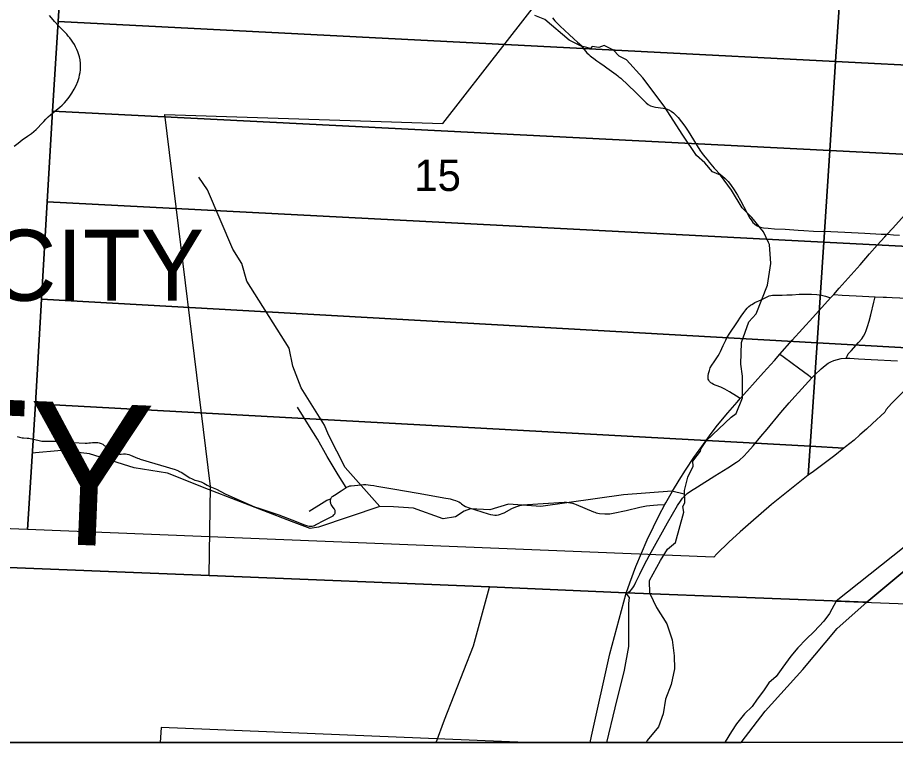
# Model space of a CAD drawing. Extents: x 0 to 34, y 0 to 22.
# Drawn here: x 25.938 to 27.11, y 14.1 to 15.067 of the extents above; entities that cross this region are included whole.
import ezdxf

# ---------------------------------------------------------------- set-up
doc = ezdxf.new("R2010")
doc.units = 0
for name, color, linetype in [('GM_X_City_Street', 7, 'Continuous'), ('GM_X_Corporation', 7, 'Continuous'), ('GM_X_Corporation_Text', 7, 'Continuous'), ('GM_X_County_Road', 7, 'Continuous'), ('GM_X_County_Text', 7, 'Continuous'), ('GM_X_Major_River', 7, 'Continuous'), ('GM_X_Minor_River', 7, 'Continuous'), ('GM_X_Section', 7, 'Continuous'), ('GM_X_Section_Text', 7, 'Continuous'), ('GM_X_State_Route', 7, 'Continuous'), ('GM_X_State_Shield', 7, 'Continuous'), ('GM_X_Township_Road', 7, 'Continuous'), ('SH_Cut_Line', 7, 'Continuous'), ('SH_Data', 7, 'Continuous')]:
    doc.layers.add(name, color=color, linetype=linetype)

msp = doc.modelspace()

# ---------------------------------------------------------------- linework, layer by layer
at = {"layer": 'GM_X_City_Street'}
for points in [[(26.6519, 15.0666), (26.6552, 15.0627), (26.6583, 15.0594), (26.6618, 15.0561), (26.6687, 15.0496), (26.6742, 15.0444), (26.6805, 15.0385), (26.6856, 15.034), (26.688, 15.0319), (26.6897, 15.0301), (26.6909, 15.0288), (26.6922, 15.0275), (26.6944, 15.0244), (26.6961, 15.0219), (26.6978, 15.0201), (26.7005, 15.0176), (26.7023, 15.016), (26.7042, 15.0144), (26.7072, 15.0122), (26.7112, 15.0094), (26.7153, 15.0065), (26.7208, 15.0026), (26.7244, 15.0001), (26.7309, 14.9954), (26.7339, 14.9932), (26.7368, 14.991), (26.7393, 14.9891), (26.7407, 14.9879), (26.7431, 14.986), (26.7454, 14.9839), (26.7507, 14.9789), (26.765, 14.9651), (26.7728, 14.9572), (26.7768, 14.9533), (26.7798, 14.9511), (26.783, 14.9493), (26.786, 14.9482), (26.7896, 14.9473), (26.7995, 14.9461), (26.8037, 14.9451), (26.8072, 14.9439), (26.8105, 14.9421), (26.8135, 14.9399), (26.8163, 14.9374), (26.8196, 14.9338), (26.8242, 14.9279), (26.8285, 14.9219), (26.833, 14.9152), (26.8487, 14.8901), (26.8518, 14.8856), (26.8551, 14.8812), (26.8583, 14.8775), (26.861, 14.8741), (26.8678, 14.8661), (26.8703, 14.8633), (26.8741, 14.8593), (26.8764, 14.8572), (26.8788, 14.8553), (26.8821, 14.8526), (26.8835, 14.8514), (26.8864, 14.8484), (26.8893, 14.8444), (26.8942, 14.8372), (26.8988, 14.8299), (26.9029, 14.8229), (26.9113, 14.807), (26.9155, 14.7993), (26.9178, 14.7957), (26.9194, 14.7937), (26.9216, 14.7916), (26.924, 14.7897), (26.9268, 14.7883), (26.9297, 14.7873), (26.9334, 14.7866), (26.9396, 14.7859), (26.9483, 14.7853), (26.9625, 14.7846), (26.98, 14.7834), (26.9874, 14.7829), (27.0004, 14.7822), (27.0233, 14.7815), (27.042, 14.7807), (27.0687, 14.7794), (27.0904, 14.7782), (27.0986, 14.7778), (27.1069, 14.7772), (27.1149, 14.7767)], [(26.9025, 14.5586), (26.8973, 14.5619), (26.8883, 14.5675), (26.8819, 14.5713), (26.8768, 14.5738), (26.8704, 14.5763), (26.867, 14.5776), (26.8649, 14.5788), (26.8634, 14.5797), (26.8617, 14.5813), (26.8604, 14.5832), (26.8598, 14.5848), (26.8596, 14.5866), (26.8597, 14.589), (26.8602, 14.592), (26.8613, 14.5962), (26.8626, 14.5996), (26.8646, 14.6033), (26.8676, 14.6079), (26.873, 14.6156), (26.8749, 14.6188), (26.8763, 14.6216), (26.8797, 14.6296), (26.8832, 14.6368), (26.8847, 14.6395), (26.8888, 14.6458), (26.898, 14.6598), (26.9037, 14.6684), (26.9072, 14.6737), (26.9098, 14.6771), (26.9117, 14.6794), (26.9139, 14.6815), (26.9162, 14.6833), (26.9179, 14.6843), (26.9202, 14.6857), (26.9221, 14.6867), (26.9306, 14.6904), (26.9376, 14.6941), (26.9409, 14.6956), (26.9432, 14.6962), (26.9456, 14.6966), (26.9493, 14.6968), (26.9586, 14.6967), (26.9648, 14.6969), (26.9717, 14.6973), (26.981, 14.6978), (26.9896, 14.6981), (26.9977, 14.6978), (27.0046, 14.6974), (27.011, 14.6965), (27.0161, 14.6954), (27.023, 14.6929)], [(27.0272, 14.6976), (27.0383, 14.6967), (27.0572, 14.6959), (27.0742, 14.6949), (27.0823, 14.6944), (27.0934, 14.694), (27.0978, 14.6939), (27.1052, 14.6935), (27.1356, 14.6924), (27.1548, 14.6916), (27.1641, 14.6915), (27.1765, 14.6913), (27.187, 14.6911), (27.2031, 14.6903), (27.2205, 14.6894), (27.2254, 14.6892)], [(27.0441, 14.6124), (27.0447, 14.6143), (27.0455, 14.6163), (27.0467, 14.6183), (27.0505, 14.6223), (27.0604, 14.6334), (27.0647, 14.6386), (27.0671, 14.6421), (27.0692, 14.6458), (27.0707, 14.6497), (27.0723, 14.655), (27.0744, 14.6621), (27.0767, 14.6704), (27.0808, 14.6873), (27.0816, 14.6909), (27.0823, 14.6944)], [(26.9552, 14.6178), (26.9597, 14.6147), (26.9717, 14.6061), (26.9802, 14.5999), (26.9935, 14.5899), (26.998, 14.5863)], [(26.7504, 14.2992), (26.7525, 14.2999), (26.7541, 14.301), (26.7559, 14.3023), (26.7576, 14.304), (26.7593, 14.3062), (26.7609, 14.3089), (26.7634, 14.3139), (26.7684, 14.3245), (26.7751, 14.3381), (26.7837, 14.3539), (26.8055, 14.3928), (26.8188, 14.4159), (26.8226, 14.4217), (26.8256, 14.4257), (26.8286, 14.429), (26.8319, 14.432), (26.836, 14.435), (26.8455, 14.4409), (26.8687, 14.4556), (26.8859, 14.4665), (26.8974, 14.4737), (26.9013, 14.4766), (26.9072, 14.482), (26.9124, 14.4872), (26.9197, 14.4955), (26.9301, 14.5079), (26.9383, 14.518), (26.9565, 14.5401), (26.968, 14.5532), (26.9754, 14.5615), (26.9804, 14.567), (26.998, 14.5863), (27.002, 14.5903), (27.0106, 14.5985), (27.0159, 14.6029), (27.02, 14.6058), (27.0234, 14.6077), (27.0274, 14.6095), (27.0323, 14.611), (27.0372, 14.612), (27.0423, 14.6124), (27.0441, 14.6124), (27.0485, 14.6124), (27.0603, 14.6119), (27.0773, 14.6109), (27.1124, 14.609)], [(26.3767, 14.44), (26.3663, 14.457), (26.3516, 14.4813), (26.3384, 14.5045), (26.328, 14.5214), (26.3119, 14.5473)], [(26.3272, 14.4086), (26.3439, 14.4187), (26.3508, 14.423), (26.3522, 14.4236), (26.3536, 14.4241), (26.3548, 14.4244), (26.3561, 14.4245)]]:
    msp.add_lwpolyline(points, dxfattribs=at)
at = {"layer": 'GM_X_Corporation'}
msp.add_lwpolyline([(27.1862, 14.3829), (27.0716, 14.2873), (26.7502, 14.2997), (26.568, 14.3076), (26.1939, 14.3226), (26.1957, 14.4415), (26.1347, 14.9377), (26.5056, 14.9255), (26.755, 15.246), (26.8156, 15.2429), (26.8743, 15.1546), (26.9519, 15.2596), (27.2149, 15.247)], dxfattribs=at)
at = {"layer": 'GM_X_County_Road'}
msp.add_lwpolyline([(26.7244, 14.1), (26.7357, 14.1463), (26.7482, 14.1963), (26.7541, 14.2282), (26.7537, 14.259), (26.7537, 14.2853), (26.7547, 14.2932), (26.7504, 14.2992)], dxfattribs=at)
at = {"layer": 'GM_X_County_Text'}
msp.add_lwpolyline([(23.8372, 20.6485), (23.8372, 14.4177), (24.4263, 14.3937), (25.7269, 14.3414), (26.0929, 14.3266), (26.1939, 14.3226), (26.568, 14.3076), (26.7502, 14.2997), (27.0716, 14.2873), (27.1862, 14.3829)], dxfattribs=at)
msp.add_lwpolyline([(23.8372, 14.4177), (23.8372, 14.1), (26.9036, 14.1), (26.9358, 14.1416), (26.9861, 14.1972), (27.0318, 14.2519), (27.0716, 14.2873), (26.7502, 14.2997), (26.568, 14.3076), (26.1939, 14.3226), (26.0929, 14.3266), (25.7269, 14.3414), (24.4263, 14.3937)], close=True, dxfattribs=at)
at = {"layer": 'GM_X_Major_River'}
msp.add_line((27.0305, 14.2886), (27.4015, 14.2737), dxfattribs=at)
for points in [[(27.1214, 14.3605), (27.0305, 14.2886)], [(27.0305, 14.2886), (27.0215, 14.2718), (27.014, 14.2616), (27.0012, 14.2479), (26.9903, 14.2376), (26.9793, 14.2261), (26.9699, 14.2151), (26.9594, 14.2006), (26.9504, 14.1881), (26.9406, 14.1797), (26.9334, 14.169), (26.9251, 14.1576), (26.9184, 14.1481), (26.9082, 14.1382), (26.8973, 14.1248), (26.8909, 14.1146), (26.8823, 14.1009), (26.8816, 14.1)]]:
    msp.add_lwpolyline(points, dxfattribs=at)
at = {"layer": 'GM_X_Minor_River'}
for points in [[(26.816, 14.3666), (26.8273, 14.4073), (26.8258, 14.4149), (26.8288, 14.4195), (26.828, 14.4362), (26.8325, 14.4537), (26.8397, 14.4685), (26.8393, 14.475), (26.8495, 14.4887), (26.8506, 14.4921), (26.8574, 14.5028), (26.8903, 14.5337), (26.8971, 14.539), (26.9054, 14.5595), (26.9057, 14.5888), (26.9031, 14.6044), (26.9042, 14.6337), (26.914, 14.6611), (26.9238, 14.6717), (26.9389, 14.7098), (26.9434, 14.739), (26.9415, 14.7641), (26.9403, 14.7668), (26.9335, 14.7812), (26.918, 14.8002), (26.9051, 14.8131), (26.8908, 14.8366), (26.876, 14.8567), (26.8654, 14.8612), (26.8552, 14.873), (26.8442, 14.8829), (26.826, 14.9102), (26.8011, 14.9489), (26.7727, 14.9864), (26.7507, 15.0107), (26.7409, 15.0156), (26.733, 15.024), (26.7307, 15.0247), (26.7209, 15.0296), (26.7137, 15.027), (26.705, 15.0285), (26.7027, 15.0258), (26.6895, 15.0292), (26.6743, 15.0368), (26.6418, 15.0644), (26.6286, 15.0697)], [(26.8278, 14.4313), (26.8111, 14.435), (26.7466, 14.4303), (26.6366, 14.4148), (26.5932, 14.4177), (26.5684, 14.4105), (26.5427, 14.4117), (26.5343, 14.4085), (26.5228, 14.4009), (26.5061, 14.3984), (26.4668, 14.4126), (26.44, 14.4145), (26.4219, 14.4147), (26.3755, 14.4667), (26.353, 14.5104), (26.3477, 14.5234), (26.3167, 14.573), (26.3055, 14.6019), (26.3009, 14.6259), (26.2901, 14.643), (26.2443, 14.7155), (26.2374, 14.7388), (26.2255, 14.7582), (26.192, 14.8371), (26.1804, 14.8542)], [(26.4218, 14.4148), (26.3398, 14.387), (26.3288, 14.3854), (26.3037, 14.3949), (26.1931, 14.4376), (26.1382, 14.4594), (26.0938, 14.4662), (26.0343, 14.4848), (25.997, 14.4894), (25.9576, 14.486)], [(26.7818, 14.2986), (26.7816, 14.3159), (26.796, 14.3426), (26.8054, 14.3578), (26.816, 14.3666)], [(26.7818, 14.2986), (26.7908, 14.2802), (26.8044, 14.2581), (26.8119, 14.2368), (26.8142, 14.2155), (26.8149, 14.198), (26.8103, 14.1775), (26.8026, 14.1578), (26.7995, 14.1381), (26.7934, 14.1206), (26.7782, 14.1024), (26.777, 14.1)]]:
    msp.add_lwpolyline(points, dxfattribs=at)
at = {"layer": 'GM_X_Section'}
for points in [[(24.9883, 15.4512), (26.0137, 15.3999), (25.9993, 15.1693), (25.9925, 15.0615), (25.9851, 14.9419), (25.9779, 14.8211), (25.9703, 14.6911), (25.9621, 14.5516), (25.9518, 14.384), (24.9287, 14.4241)], [(25.9993, 15.1693), (26.2311, 15.157), (27.0368, 15.114), (27.0298, 15.0085), (25.9925, 15.0615)], [(27.0368, 15.114), (27.5553, 15.0864), (27.5463, 15.0789), (27.5274, 15.0629), (27.4979, 15.0356), (27.4752, 15.0143), (27.4642, 15.0048), (27.447, 14.9872), (27.0298, 15.0085)], [(27.0298, 15.0085), (27.022, 14.8897), (25.9851, 14.9419), (25.9925, 15.0615)], [(27.447, 14.9872), (27.4438, 14.9839), (27.4294, 14.9703), (27.4192, 14.9608), (27.4098, 14.9505), (27.3965, 14.9346), (27.3799, 14.9137), (27.378, 14.9114), (27.3701, 14.9027), (27.3576, 14.892), (27.3478, 14.8833), (27.3387, 14.8769), (27.3345, 14.8753), (27.3315, 14.8746), (27.3262, 14.8749), (27.3237, 14.8752), (27.3209, 14.8747), (27.022, 14.8897), (27.0298, 15.0085)], [(25.9851, 14.9419), (27.022, 14.8897), (27.0139, 14.7675), (25.9779, 14.8211)], [(27.022, 14.8897), (27.3209, 14.8747), (27.3201, 14.872), (27.3206, 14.8702), (27.322, 14.8685), (27.3251, 14.8673), (27.3277, 14.8647), (27.33, 14.8609), (27.3304, 14.8586), (27.3304, 14.853), (27.3274, 14.8416), (27.3263, 14.8374), (27.3149, 14.8192), (27.2908, 14.7801), (27.2738, 14.754), (27.0139, 14.7675)], [(27.0139, 14.7675), (27.005, 14.633), (25.9703, 14.6911), (25.9779, 14.8211)], [(27.2738, 14.754), (27.2674, 14.7441), (27.2492, 14.719), (27.2345, 14.6982), (27.2179, 14.6765), (27.2043, 14.6602), (27.1873, 14.6405), (27.1831, 14.6348), (27.1729, 14.6236), (27.005, 14.633), (27.0139, 14.7675)], [(25.9703, 14.6911), (27.005, 14.633), (26.9958, 14.4952), (25.9621, 14.5516)], [(27.005, 14.633), (27.1729, 14.6236), (27.1404, 14.5896), (27.1241, 14.5721), (27.1041, 14.552), (27.0973, 14.544), (27.0954, 14.5406), (27.0791, 14.5254), (27.0708, 14.5178), (27.0621, 14.5102), (27.0545, 14.5034), (27.0428, 14.4943), (27.0409, 14.4927), (26.9958, 14.4952)], [(26.9958, 14.4952), (26.9932, 14.4565), (26.9865, 14.4514), (26.9441, 14.4172), (26.9165, 14.3936), (26.9025, 14.3811), (26.8874, 14.367), (26.8715, 14.3515), (26.8673, 14.3473), (25.9518, 14.384), (25.9621, 14.5516)], [(27.0409, 14.4927), (27.0285, 14.4829), (27.0001, 14.4616), (26.9932, 14.4565), (26.9958, 14.4952)]]:
    msp.add_lwpolyline(points, close=True, dxfattribs=at)
at = {"layer": 'GM_X_State_Route'}
for points in [[(27.023, 14.6929), (27.0272, 14.6976), (27.0343, 14.7058), (27.0625, 14.7373), (27.075, 14.7519), (27.0854, 14.7634), (27.0955, 14.7744), (27.0986, 14.7778), (27.1055, 14.7855), (27.1222, 14.8039), (27.1638, 14.8507), (27.1725, 14.8605), (27.1994, 14.8907), (27.2104, 14.9034), (27.2244, 14.9193)], [(26.7504, 14.2992), (26.7551, 14.3128), (26.7634, 14.3348), (26.7707, 14.3526), (26.7784, 14.3702), (26.7866, 14.3877), (26.7944, 14.4032), (26.8019, 14.4172), (26.8032, 14.4196), (26.8121, 14.4352), (26.8211, 14.45), (26.8295, 14.4631), (26.8407, 14.4802), (26.8511, 14.4949), (26.8636, 14.5119), (26.8723, 14.5232), (26.8858, 14.5395), (26.8983, 14.554), (26.9025, 14.5586), (26.9112, 14.5684), (26.9335, 14.5934), (26.948, 14.6096), (26.9552, 14.6178), (26.972, 14.6365), (26.9994, 14.667), (27.023, 14.6929)], [(26.7023, 14.1), (26.7042, 14.1082), (26.7285, 14.218), (26.7504, 14.2992)]]:
    msp.add_lwpolyline(points, dxfattribs=at)
at = {"layer": 'GM_X_State_Shield'}
msp.add_lwpolyline([(26.1286, 14.1), (26.6166, 14.1), (26.1298, 14.12)], close=True, dxfattribs=at)
at = {"layer": 'GM_X_Township_Road'}
for points in [[(25.934, 14.8952), (25.9392, 14.8995), (25.9446, 14.9037), (25.9517, 14.9086), (25.9569, 14.9122), (25.9603, 14.9149), (25.9634, 14.9178), (25.966, 14.9204), (25.9695, 14.9241), (25.9734, 14.9284), (25.9762, 14.9316), (25.9791, 14.9343), (25.9822, 14.9372), (25.9856, 14.9399), (25.995, 14.9475), (25.998, 14.9501), (26.0009, 14.9531), (26.0037, 14.9563), (26.0071, 14.9606), (26.0108, 14.9662), (26.014, 14.9715), (26.0165, 14.9764), (26.0186, 14.9815), (26.0196, 14.9843), (26.0204, 14.9868), (26.0212, 14.9904), (26.0218, 14.9938), (26.0222, 14.9972), (26.0224, 15.0011), (26.0223, 15.0058), (26.0219, 15.0104), (26.0211, 15.0146), (26.0199, 15.0184), (26.0188, 15.0214), (26.0176, 15.0242), (26.0159, 15.0279), (26.0142, 15.0309), (26.0123, 15.034), (26.0103, 15.037), (26.0083, 15.0397), (26.0061, 15.0422), (26.0039, 15.0447), (25.9933, 15.0553), (25.9878, 15.0615), (25.9835, 15.0664), (25.981, 15.0695)], [(25.9379, 14.5082), (25.9408, 14.5072), (25.9426, 14.5067), (25.9444, 14.5064), (25.9462, 14.5062), (25.9512, 14.506), (25.9534, 14.5057), (25.9553, 14.5053), (25.9573, 14.5049), (25.967, 14.5027), (25.9688, 14.5023), (25.9707, 14.5021), (25.9758, 14.5017), (25.9926, 14.502), (26.0121, 14.4999), (26.0287, 14.4994), (26.0314, 14.4994), (26.0336, 14.4996), (26.0358, 14.4998), (26.0384, 14.5001), (26.0407, 14.5003), (26.0429, 14.5002), (26.0453, 14.4999), (26.0473, 14.4996), (26.0498, 14.4988), (26.052, 14.4977), (26.054, 14.4963), (26.0557, 14.495), (26.062, 14.4896), (26.0639, 14.4879), (26.0659, 14.4866), (26.0682, 14.4855), (26.0712, 14.4849), (26.0743, 14.4846), (26.0766, 14.4847), (26.0796, 14.4849), (26.0826, 14.4849), (26.0847, 14.4846), (26.0867, 14.4841), (26.089, 14.4834), (26.0985, 14.4792), (26.1001, 14.4786), (26.1018, 14.478), (26.1485, 14.464), (26.1509, 14.4633), (26.1529, 14.4624), (26.1545, 14.4616), (26.1566, 14.4605), (26.1683, 14.4531), (26.1706, 14.4519), (26.173, 14.4508), (26.1749, 14.45), (26.177, 14.4493), (26.1789, 14.4488), (26.1814, 14.4482), (26.1833, 14.4476), (26.1853, 14.4468), (26.1869, 14.446), (26.1912, 14.4433), (26.1959, 14.441), (26.1969, 14.4406)], [(26.3617, 14.4051), (26.3621, 14.406), (26.3622, 14.4069), (26.3622, 14.4076), (26.3621, 14.4085), (26.3619, 14.4093), (26.3616, 14.4102), (26.3612, 14.411), (26.3607, 14.4118), (26.3587, 14.4148), (26.3569, 14.4175), (26.3564, 14.4184), (26.3561, 14.4193), (26.3558, 14.4203), (26.3557, 14.4215), (26.3557, 14.4225), (26.3559, 14.4235), (26.3561, 14.4245), (26.3564, 14.4253), (26.3567, 14.426), (26.3571, 14.4266), (26.3576, 14.4274), (26.3582, 14.428), (26.359, 14.4286), (26.3611, 14.43), (26.3699, 14.4357), (26.3767, 14.44), (26.3785, 14.4409), (26.3801, 14.4416), (26.3818, 14.4421), (26.3836, 14.4424), (26.3966, 14.4437), (26.4, 14.4439), (26.403, 14.4439), (26.4063, 14.4437), (26.4094, 14.4433), (26.4135, 14.4426), (26.4175, 14.442), (26.4389, 14.4381), (26.4727, 14.4325), (26.5099, 14.4259), (26.5127, 14.4254), (26.5157, 14.4248), (26.5194, 14.4238), (26.5228, 14.4228), (26.525, 14.4219), (26.5272, 14.4208), (26.5292, 14.4195), (26.5306, 14.4184), (26.5322, 14.417), (26.5336, 14.416), (26.536, 14.4149), (26.5407, 14.413), (26.5662, 14.4048), (26.5695, 14.4039), (26.5724, 14.4034), (26.5751, 14.4031), (26.5775, 14.4032), (26.5799, 14.4036), (26.5826, 14.4043), (26.5851, 14.4053), (26.5876, 14.4065), (26.5976, 14.4121), (26.6008, 14.4136), (26.6044, 14.4149), (26.6085, 14.416), (26.6129, 14.4168), (26.6186, 14.4176), (26.6675, 14.4204), (26.6706, 14.4203), (26.6733, 14.4202), (26.6761, 14.4198), (26.6788, 14.4193), (26.6812, 14.4185), (26.6836, 14.4176), (26.7067, 14.4077), (26.7087, 14.407), (26.7105, 14.4064), (26.7125, 14.4059), (26.7149, 14.4056), (26.7219, 14.4051)], [(26.1969, 14.4406), (26.2036, 14.4377), (26.2153, 14.4318), (26.2404, 14.4205), (26.2547, 14.4145), (26.2602, 14.4124), (26.2869, 14.4034), (26.3043, 14.397), (26.3211, 14.3902), (26.324, 14.3893), (26.3256, 14.3889), (26.3274, 14.3886), (26.329, 14.3884), (26.3302, 14.3884), (26.3314, 14.3886), (26.333, 14.389), (26.3345, 14.3896), (26.336, 14.3903), (26.348, 14.3963), (26.3584, 14.4017), (26.3596, 14.4025), (26.3605, 14.4034), (26.3613, 14.4043), (26.3617, 14.4051)], [(26.7219, 14.4051), (26.7239, 14.4049), (26.7264, 14.4049), (26.7287, 14.405), (26.7306, 14.4053), (26.733, 14.4057), (26.7504, 14.4096), (26.7684, 14.4137), (26.7731, 14.4147), (26.7775, 14.4156), (26.782, 14.4162), (26.787, 14.4166), (26.7923, 14.4169), (26.8019, 14.4172)], [(26.497, 14.1), (26.508, 14.1301), (26.5466, 14.2289), (26.5682, 14.307)]]:
    msp.add_lwpolyline(points, dxfattribs=at)
at = {"layer": 'SH_Cut_Line'}
msp.add_lwpolyline([(23.8372, 20.9), (23.8372, 14.4177), (24.4263, 14.3937), (25.7269, 14.3414), (26.0929, 14.3266), (26.1939, 14.3226), (26.568, 14.3076), (26.7502, 14.2997), (27.0716, 14.2873), (27.1862, 14.3829)], dxfattribs=at)
msp.add_lwpolyline([(23.8372, 14.4177), (23.8372, 14.1), (26.9036, 14.1), (26.9358, 14.1416), (26.9861, 14.1972), (27.0318, 14.2519), (27.0716, 14.2873), (26.7502, 14.2997), (26.568, 14.3076), (26.1939, 14.3226), (26.0929, 14.3266), (25.7269, 14.3414), (24.4263, 14.3937)], close=True, dxfattribs=at)
at = {"layer": 'SH_Data'}
msp.add_lwpolyline([(23.8372, 20.9), (30.6372, 20.9), (30.6372, 14.1), (23.8372, 14.1)], close=True, dxfattribs=at)

# ---------------------------------------------------------------- texts
at = {"layer": 'GM_X_Corporation_Text'}
msp.add_text('CROWN CITY', height=0.0947, rotation=0, dxfattribs=at).set_placement((25.3712, 14.6892))
at = {"layer": 'GM_X_County_Text'}
msp.add_text('GALLIA COUNTY', height=0.189394, rotation=357.6921, dxfattribs=at).set_placement((24.0901, 14.4413))
at = {"layer": 'GM_X_Section_Text'}
msp.add_text('15', height=0.04186, rotation=0, dxfattribs=at).set_placement((26.4676, 14.8356))

doc.saveas('drawing.dxf')
